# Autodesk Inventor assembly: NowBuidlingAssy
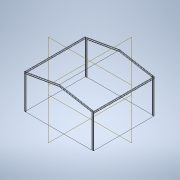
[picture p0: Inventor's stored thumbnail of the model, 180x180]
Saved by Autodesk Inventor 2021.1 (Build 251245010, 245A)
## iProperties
_SolveAssemblyDoc: Frame Generator Solve Assembly
_Version: 25.0.0
Created: 2020-12
Part Number: NowBuidlingAssy
Document SubType Name: Assembly
Designer: BALA
Author: BALA
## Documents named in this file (3)
- H:\Inventor\Now Building\NowBuidlingAssy.iam
- H:\Inventor\Now Building\BuildSkeleton.ipt
- H:\Inventor\Now Building\NowBuidlingAssy\Frame\Frame 1609038906220.iam
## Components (2 placed, 2 different names)
1. BuildSkeleton:1
2. Frame 1609038906220:1 [sub-assembly]
## Named parameters: OFFSET_A = 1 mm
